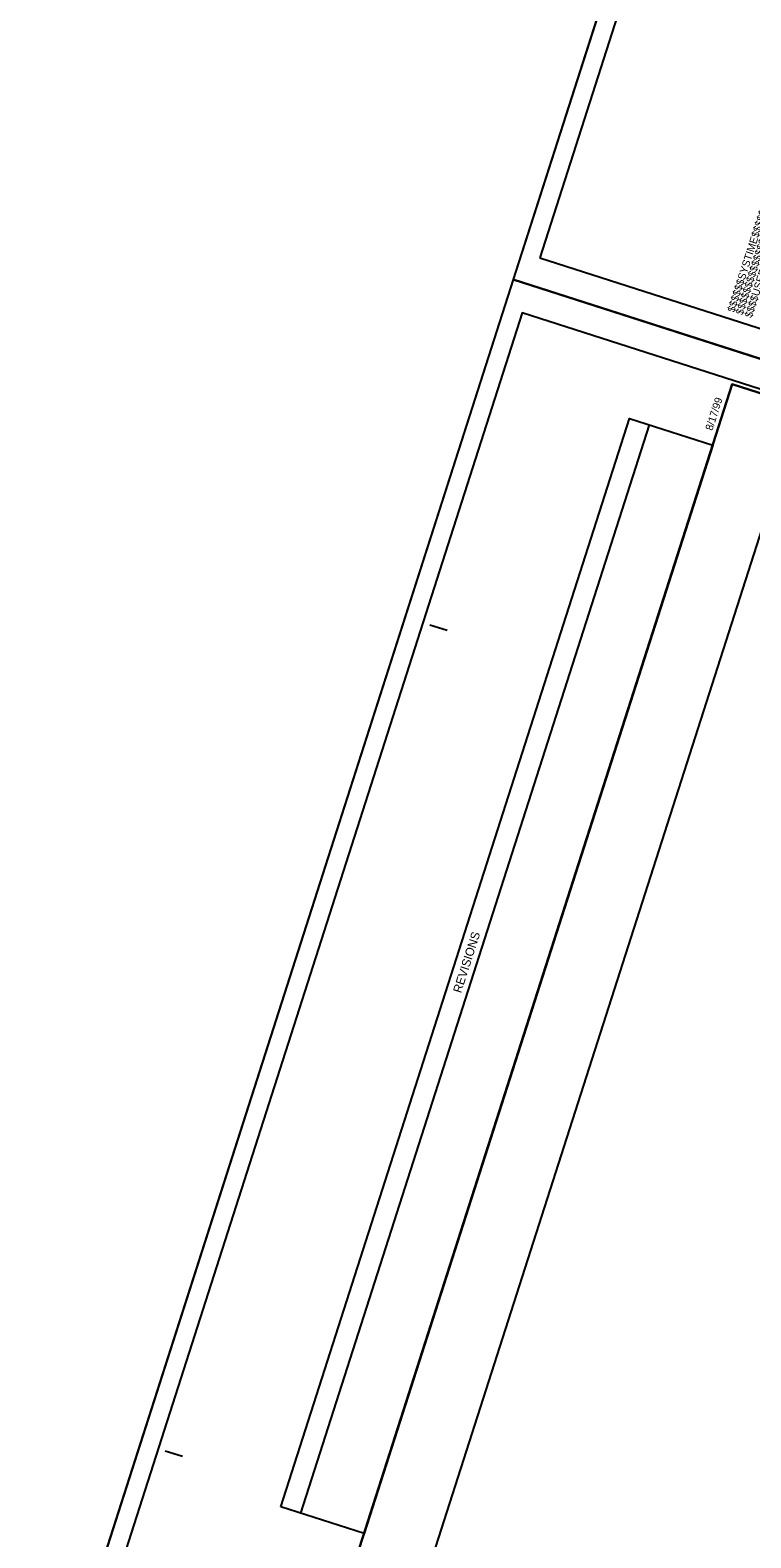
# Model space of a CAD drawing. Extents: x 928111 to 937215, y 684320 to 686530.
# Drawn here: x 933610.98 to 933630.93, y 684674.31 to 684716.03 of the extents above; entities that cross this region are included whole.
import ezdxf

# ---------------------------------------------------------------- set-up
doc = ezdxf.new("R2010")
doc.units = 0
for name, color, linetype in [('Sheet Block Revision CELL', 7, 'Continuous'), ('Sheet Clip Boundary CELL', 7, 'Continuous'), ('Sheet Cutting Line CELL', 7, 'Continuous'), ('Sheet Layout Plan Border', 7, 'Continuous'), ('Sheet Plan CELL', 7, 'Continuous'), ('Sheet Plan Layout CELL', 7, 'Continuous'), ('Sheet Plot Border Inside CELL', 7, 'Continuous'), ('Sheet Plot Border Outside CELL', 7, 'Continuous')]:
    doc.layers.add(name, color=color, linetype=linetype)

msp = doc.modelspace()

# ---------------------------------------------------------------- linework, layer by layer
at = {"layer": 'Sheet Block Revision CELL'}
msp.add_line((933618.473, 684674.991), (933628.126, 684705.107), dxfattribs=at)
msp.add_lwpolyline([(933617.918, 684675.168), (933627.572, 684705.284), (933629.878, 684704.546), (933620.225, 684674.43)], close=True, dxfattribs=at)
at = {"layer": 'Sheet Clip Boundary CELL'}
msp.add_lwpolyline([(933619.504, 684665.63), (933672.831, 684648.536), (933683.069, 684680.476), (933675.86, 684682.787), (933678.442, 684690.842), (933632.324, 684705.625)], close=True, dxfattribs=at)
at = {"layer": 'Sheet Cutting Line CELL'}
for p, q in [((933637.722, 684750.835), (933624.352, 684709.125)), ((933624.352, 684709.125), (933610.982, 684667.415)), ((933624.352, 684709.125), (933688.478, 684688.57)), ((933688.478, 684688.57), (933624.352, 684709.125))]:
    msp.add_line(p, q, dxfattribs=at)
at = {"layer": 'Sheet Layout Plan Border'}
msp.add_lwpolyline([(933619.504, 684665.63), (933672.831, 684648.536), (933683.069, 684680.476), (933675.86, 684682.787), (933678.442, 684690.842), (933632.324, 684705.625)], close=True, dxfattribs=at)
at = {"layer": 'Sheet Plan CELL'}
for p, q in [((933630.419, 684706.236), (933630.419, 684706.236)), ((933622.046, 684699.573), (933622.523, 684699.421)), ((933614.721, 684676.718), (933615.197, 684676.565))]:
    msp.add_line(p, q, dxfattribs=at)
for points in [[(933687.557, 684687.921), (933630.419, 684706.236), (933617.599, 684666.24), (933674.736, 684647.926)], [(933617.599, 684666.24), (933630.418, 684706.235), (933679.936, 684690.364), (933678.104, 684684.648), (933685.724, 684682.205), (933674.736, 684647.926)]]:
    msp.add_lwpolyline(points, close=True, dxfattribs=at)
at = {"layer": 'Sheet Plan Layout CELL'}
msp.add_lwpolyline([(933630.418, 684706.235), (933617.599, 684666.24), (933674.736, 684647.926), (933684.973, 684679.865), (933675.86, 684682.787), (933678.442, 684690.842)], close=True, dxfattribs=at)
at = {"layer": 'Sheet Plot Border Inside CELL'}
for points in [[(933625.091, 684709.728), (933688.551, 684689.388), (933701.432, 684729.573), (933637.973, 684749.914)], [(933611.722, 684668.018), (933675.181, 684647.678), (933688.063, 684687.863), (933624.603, 684708.204)]]:
    msp.add_lwpolyline(points, close=True, dxfattribs=at)
at = {"layer": 'Sheet Plot Border Outside CELL'}
for points in [[(933624.352, 684709.125), (933688.478, 684688.57), (933701.848, 684730.28), (933637.722, 684750.835)], [(933610.982, 684667.415), (933675.109, 684646.86), (933688.478, 684688.57), (933624.352, 684709.125)]]:
    msp.add_lwpolyline(points, close=True, dxfattribs=at)

# ---------------------------------------------------------------- texts
at = {"layer": 'Sheet Block Revision CELL'}
msp.add_text('REVISIONS', height=0.24, rotation=72.2273, dxfattribs=at).set_placement((933622.911, 684689.368))
at = {"layer": 'Sheet Plan CELL'}
for s, p in [('$$$$$$$$$$$$$$$$DGN$$$$$$$$$$$$$$$$', (933630.706, 684708.133)), ('$$$$$$SYSTIME$$$$$', (933630.475, 684708.206)), ('$$$$USERNAME$$$$', (933630.956, 684708.054)), ('8/17/99', (933629.866, 684704.933))]:
    msp.add_text(s, height=0.21, rotation=72.2273, dxfattribs=at).set_placement(p)

doc.saveas('drawing.dxf')
